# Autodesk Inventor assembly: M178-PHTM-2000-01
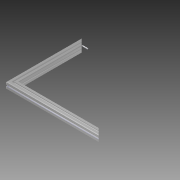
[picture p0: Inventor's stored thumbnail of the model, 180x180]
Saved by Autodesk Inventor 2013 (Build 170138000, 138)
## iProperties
Created: 2004-11
Part Number: M178-PHTM-2000-01
Document SubType Name: Assembly
Designer: Autodesk, Inc.
Manufacturer: Standard
Standards Organization: Custom
Description: PHANTOM, CABINET BASE ANGLE
Mass: 1392.78 g
Surface Area: 5653.08 cm^2
Volume: 515.586 cm^3
Density: 2.70136 g/cm^3
CAGE: 1LJX3
Dept. ID: Product Design
Description #2: ---
Finish #1: ---
Finish #2: ---
Material ID: ---
Project Number: ---
Author: Autodesk, Inc.
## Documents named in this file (7)
- Z:\_DATEN\Test Station\Components\M178-2000-Base_Phantom.iam
- Z:\_DATEN\Test Station\Components\M178-2003.ipt
- Z:\_DATEN\Test Station\Components\M178-2004.ipt
- Z:\_DATEN\Test Station\Components\20-128 Mitre Connector.ipt
- Z:\_DATEN\Test Station\Components\24-506-6F.ipt
- C:\Users\kelleyb.ADS\Desktop\Samples MIGRATED 2009 224 RTM_1\Standard Parts\Test Station Content\Fastners\24-5XX-YY Setscrews.ipt
- C:\Users\kelleyb.ADS\Desktop\Samples MIGRATED 2009 224 RTM_1\Standard Parts\Test Station Content\Extrusions\40 Series Profiles.ipt
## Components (8 placed, 4 different names)
1. 24-506-6F:1
2. 24-506-6F:2
3. 24-506-6F:3
4. 24-506-6F:4
5. M178-2003:1
6. M178-2004:2
7. 20-128 Mitre Connector:1
8. 20-128 Mitre Connector:2
